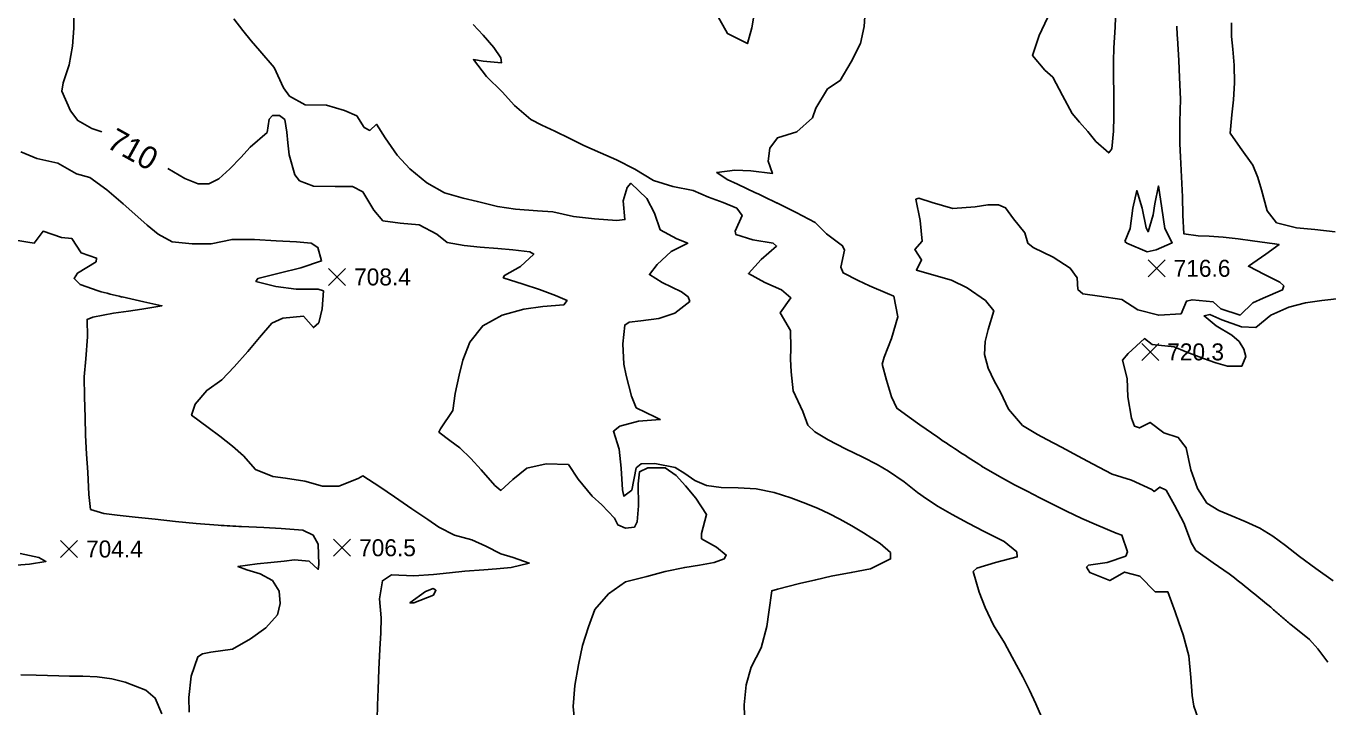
# Model space of a CAD drawing. Extents: x 2566079 to 2571326, y 424054 to 426896.
# Drawn here: x 2568340 to 2569490, y 425294 to 425896 of the extents above; entities that cross this region are included whole.
import ezdxf

# ---------------------------------------------------------------- set-up
doc = ezdxf.new("R2010")
doc.units = 0
for name, color, linetype in [('Contour_ADS_Label_Major', 7, 'Continuous'), ('Contour_ADS_Major', 7, 'Continuous'), ('Contour_ADS_Minor', 7, 'Continuous'), ('Contour_ADS_Spot_Elevation', 7, 'Continuous')]:
    doc.layers.add(name, color=color, linetype=linetype)

# ---------------------------------------------------------------- blocks, each defined once
blk = doc.blocks.new('S750')
at = {"layer": 'Contour_ADS_Spot_Elevation'}
for p, q in [((-0.5, 0.498), (0.5, -0.498)), ((-0.498, -0.5), (0.498, 0.5))]:
    blk.add_line(p, q, dxfattribs=at)

msp = doc.modelspace()

# ---------------------------------------------------------------- linework, layer by layer
at = {"layer": 'Contour_ADS_Major'}
for points in [[(2568338.3, 425981.8), (2568349.5, 425973), (2568362.5, 425958.9), (2568373.6, 425945.3), (2568379.5, 425938), (2568380.8, 425925.3), (2568381.9, 425909.7), (2568381.7, 425893.8), (2568380.6, 425877.8), (2568377.6, 425861.3), (2568372.3, 425845.4), (2568371.3, 425838.1), (2568378.8, 425820.9), (2568385.3, 425812.2), (2568397.8, 425805.3), (2568405.8, 425802.5), (2568406.5, 425802.3)], [(2569404.4, 425898.6), (2569404.5, 425886.6), (2569405.7, 425875.2), (2569406.9, 425861), (2569407.3, 425845.5), (2569406.3, 425830.5), (2569404.7, 425817.4), (2569403.2, 425801), (2569412.3, 425788.4), (2569423.4, 425772.7), (2569427.8, 425761.9), (2569431, 425751), (2569436, 425732.4), (2569444.3, 425722), (2569462, 425717.5), (2569478.1, 425716.1), (2569496.2, 425714)], [(2568464.8, 425769.9), (2568479.9, 425761), (2568491.8, 425756.2), (2568501.2, 425756.2), (2568510, 425760.8), (2568519.6, 425769.5), (2568529.3, 425779.7), (2568537.7, 425788.7), (2568552.6, 425801.7), (2568554.5, 425813.3), (2568557.4, 425816.6), (2568563.6, 425816.8), (2568568.3, 425813), (2568570, 425802), (2568570.8, 425792.6), (2568572, 425781.9), (2568577, 425764.4), (2568581.3, 425759.1), (2568593.7, 425754.2), (2568612.8, 425754), (2568628.1, 425754), (2568637.2, 425749.2), (2568647, 425733.2), (2568654.9, 425723.5), (2568670.2, 425721.6), (2568686.8, 425720), (2568702.5, 425711.8), (2568711.5, 425704.6), (2568726.8, 425701.9), (2568740.9, 425700.5), (2568756.4, 425699.1), (2568769.5, 425697.9), (2568784.6, 425696.2), (2568788.1, 425694.3), (2568776.5, 425683.4), (2568762.3, 425675.5), (2568761.2, 425673.4), (2568778.8, 425667.8), (2568793.3, 425662.9), (2568807.3, 425657.8), (2568817.5, 425653.2), (2568814.7, 425649.6), (2568796.1, 425647.9), (2568779.4, 425645.5), (2568760.1, 425640.4), (2568743, 425631), (2568731.7, 425616.6), (2568725.4, 425600.7), (2568722.3, 425587.4), (2568718.7, 425571.2), (2568716.5, 425556.2), (2568705.6, 425539.8), (2568704.3, 425537), (2568713.9, 425529.7), (2568722.7, 425523.1), (2568732.4, 425513.8), (2568741.6, 425503.7), (2568753.7, 425490), (2568759, 425485.6), (2568769.7, 425495.3), (2568782.1, 425505.2), (2568799.1, 425509.1), (2568818.8, 425508.5), (2568827.4, 425495.4), (2568839.7, 425480.6), (2568848.2, 425472.9), (2568859.5, 425461), (2568862.5, 425455.1), (2568869.1, 425452.3), (2568877, 425453.2), (2568879.6, 425457.9), (2568880.6, 425472), (2568880.5, 425491.4), (2568881.6, 425502.1), (2568889, 425505.4), (2568904.1, 425505.5), (2568913.8, 425498.6), (2568922.2, 425489.5), (2568931.3, 425478.7), (2568940.8, 425464.2), (2568936.2, 425447.4), (2568936.3, 425442.8), (2568949.6, 425435.4), (2568958.2, 425428.5), (2568956.4, 425425), (2568947.6, 425422), (2568934.6, 425419.6), (2568921.5, 425417.5), (2568904.2, 425413.9), (2568888, 425409.6), (2568869.3, 425404.8), (2568854.2, 425394.3), (2568842.1, 425380.3), (2568836.4, 425365.2), (2568831.1, 425348.6), (2568827.8, 425331.6), (2568824.5, 425313.1), (2568822.8, 425294.6), (2568824.1, 425282.6)], [(2569502.6, 425655.2), (2569484.2, 425653.3), (2569469.8, 425651.1), (2569455.2, 425647.4), (2569439.2, 425640.3), (2569426.1, 425629.3), (2569413.4, 425630.1), (2569396, 425636.3), (2569385.4, 425640.8), (2569380.3, 425639.7), (2569391, 425630.9), (2569404.9, 425622.8), (2569411.3, 425617), (2569415.4, 425610.4), (2569417.1, 425603.9), (2569413.7, 425595.4), (2569401, 425595.4), (2569390.8, 425598.3), (2569379.9, 425602.1), (2569363.5, 425608.3), (2569353.9, 425612.3), (2569334.3, 425614.4), (2569327.7, 425619.6), (2569313.2, 425606.4), (2569308.2, 425600.7), (2569312.4, 425584.5), (2569312.9, 425568.1), (2569316.3, 425549.4), (2569318.8, 425542.4), (2569323.2, 425540.7), (2569332.8, 425545.6), (2569344.7, 425536.5), (2569357.5, 425532.3), (2569364.5, 425523.1), (2569368.7, 425503.7), (2569374.5, 425487.3), (2569382.7, 425474.4), (2569393.4, 425467.7), (2569403.9, 425463.4), (2569416.7, 425458.2), (2569429.6, 425452.1), (2569441.1, 425445.1), (2569452.2, 425436.9), (2569464.5, 425427.3), (2569479, 425416.5), (2569494.2, 425405.8)]]:
    msp.add_lwpolyline(points, dxfattribs=at)
at = {"layer": 'Contour_ADS_Minor'}
for points in [[(2569080.8, 425908.4), (2569080.1, 425895.4), (2569076.8, 425880.2), (2569068.5, 425864.2), (2569058.8, 425847.6), (2569047.6, 425840.1), (2569037.2, 425823.3), (2569034.3, 425814.6), (2569020.6, 425802.2), (2569003.4, 425797), (2568996.8, 425787.7), (2568995.1, 425776.2), (2568999, 425765.4), (2568980, 425767.7), (2568965.8, 425768.4), (2568949.8, 425766.4), (2568959.1, 425760.3), (2568968.1, 425756), (2568984, 425748.5)], [(2569241.9, 425903), (2569234.7, 425887.4), (2569228.8, 425869.8), (2569239.7, 425856.8), (2569246.8, 425850.4), (2569255.1, 425834.3), (2569263.9, 425818.3), (2569270.3, 425810.7), (2569277.5, 425802.6), (2569284.7, 425793.7), (2569296.1, 425783.6), (2569298.9, 425787.1), (2569300.3, 425802.9), (2569300.6, 425815.6), (2569300.6, 425824.1), (2569300.5, 425836.4), (2569300.3, 425850.8), (2569300.4, 425864.8), (2569300.4, 425864.8), (2569300.7, 425876.4), (2569301.7, 425894.6), (2569302.4, 425911.7)], [(2568523.1, 425902), (2568531, 425891.9), (2568538.6, 425882.5), (2568546, 425873.8), (2568558.9, 425859), (2568567.2, 425841.1), (2568572.3, 425833.9), (2568586.2, 425826), (2568604.9, 425825.8), (2568620.8, 425821.1), (2568631.8, 425816.5), (2568638.3, 425806.2), (2568643.3, 425803.5), (2568649.2, 425808.9), (2568656.9, 425796.9), (2568667.6, 425781.5), (2568678.8, 425769.6), (2568693.6, 425757.2), (2568709.4, 425748.3), (2568725.9, 425743.8), (2568738.4, 425740.6), (2568756.1, 425736.3), (2568771.9, 425733.9), (2568791.4, 425732.6), (2568804.9, 425731.7), (2568823.1, 425727.6), (2568841.8, 425725.4), (2568861.6, 425723.8), (2568868.7, 425724.8), (2568867.1, 425741.2), (2568870.6, 425753.1), (2568874, 425756.9), (2568887.9, 425743.4), (2568894.8, 425730.3), (2568899.8, 425715.8), (2568914.4, 425707.8), (2568924.1, 425703.8), (2568909.6, 425696.5), (2568897.1, 425685), (2568890.3, 425676.1), (2568901.7, 425669.3), (2568918.6, 425661), (2568924.6, 425656.4), (2568926, 425652.4), (2568912.9, 425642.2), (2568898.6, 425637.3), (2568882.8, 425635.4), (2568872.3, 425634.2), (2568868.5, 425631.6), (2568866.7, 425614.9), (2568867.8, 425597), (2568869.7, 425586.9), (2568874.5, 425568.9), (2568878.7, 425558.5), (2568895.8, 425550.2), (2568899.9, 425548.1), (2568880.7, 425546.8), (2568864.1, 425542.2), (2568858.5, 425537.8), (2568863.7, 425522), (2568865.2, 425505.3), (2568866.4, 425486.2), (2568867.8, 425480.4), (2568874.7, 425485.9), (2568878.7, 425505.4), (2568883.1, 425509), (2568895.2, 425509.3), (2568913, 425505.7), (2568921.5, 425500.5), (2568930.3, 425494.4), (2568940.8, 425489.8), (2568953.8, 425488), (2568968.8, 425487.7), (2568984.7, 425486.8), (2569000.5, 425483.8), (2569015.3, 425479.1), (2569028.4, 425474.1), (2569039.3, 425469.5), (2569048.9, 425465.1), (2569058.6, 425460.2), (2569069.1, 425454.3), (2569079.5, 425448.2), (2569094, 425438.6)], [(2568734.7, 425897.2), (2568743.5, 425887.5), (2568752.8, 425876.6), (2568759, 425867.7), (2568759.7, 425863.2), (2568743.5, 425864.7), (2568734.8, 425866), (2568746.5, 425851.1), (2568760.3, 425837.7), (2568771, 425825.4), (2568785.4, 425813), (2568795.3, 425808.2), (2568806.6, 425802.8), (2568820, 425796.3), (2568832.4, 425790.3), (2568847.1, 425783.6), (2568861.3, 425777.4), (2568877.3, 425769.3), (2568893.9, 425759.4), (2568911, 425753.9), (2568928.9, 425750.5), (2568942.4, 425744.6), (2568955.5, 425739.8), (2568967.5, 425734.7), (2568972.1, 425728.3), (2568966.1, 425714.6), (2568966.7, 425711.5), (2568981.6, 425707), (2568999.6, 425704), (2569002.6, 425701.3), (2568988.9, 425689.5), (2568977.7, 425677.2), (2568992.4, 425669.1), (2569007.1, 425662.7), (2569015.2, 425655.7), (2569005.7, 425642.5), (2569015, 425626.8), (2569015.1, 425611.3), (2569015, 425601.4), (2569015.5, 425590.4), (2569017.4, 425573.4), (2569025.7, 425555.2), (2569030.1, 425543.1), (2569036.3, 425537.2), (2569048.2, 425530.1), (2569063.5, 425522.4), (2569078.8, 425515), (2569091.5, 425508.4), (2569101.5, 425502.6), (2569115.4, 425493.1), (2569127.2, 425483.8), (2569135.2, 425478), (2569145.3, 425471.4), (2569157.6, 425464.2), (2569171.9, 425456.5), (2569186, 425449.3), (2569203.8, 425440.3), (2569214.9, 425431.2), (2569215.2, 425426.8), (2569195.9, 425422), (2569179.5, 425416.9), (2569176.4, 425413.9), (2569181.7, 425395.6), (2569186.8, 425382.1), (2569194.2, 425366.4), (2569204.1, 425350.8), (2569210.8, 425338.4), (2569220.2, 425320.8), (2569226.1, 425309.2), (2569231.8, 425297.1), (2569236.6, 425285.7)], [(2568982.7, 425906.1), (2568980.9, 425894), (2568976.9, 425880.2), (2568959.4, 425889.1), (2568950, 425905.8)], [(2569356.8, 425885.1), (2569357.9, 425865.2), (2569358.6, 425850.1), (2569359.4, 425831.1), (2569359, 425811.1), (2569359, 425791.8), (2569359.6, 425780.3), (2569360.3, 425762.4), (2569361.1, 425744.9), (2569361.6, 425728.7), (2569362.4, 425712.1), (2569375, 425710.5), (2569384.9, 425710.1), (2569397, 425709.2), (2569410.3, 425707.8), (2569423.1, 425706.1), (2569442.6, 425703.4), (2569446.5, 425702.6), (2569434.7, 425694.1), (2569419.4, 425683.6), (2569433.6, 425676.3), (2569447.1, 425669.6), (2569450.7, 425666.1), (2569449.5, 425662.6), (2569432.4, 425655.2), (2569423.4, 425651.1), (2569412.2, 425640.4), (2569395.1, 425645.9), (2569388.3, 425652), (2569369.7, 425653.9), (2569364.7, 425652.7), (2569360, 425641.6), (2569340.3, 425640.3), (2569321.7, 425645.1), (2569307.6, 425654.3), (2569288, 425657.2), (2569273.2, 425659.2), (2569268.8, 425663.1), (2569268.2, 425673.4), (2569262, 425681.9), (2569247.1, 425691.6), (2569229.4, 425700.1), (2569224.6, 425703.8), (2569221.9, 425713.1), (2569211.8, 425725.5), (2569205, 425735.2), (2569198.7, 425737.9), (2569189.3, 425737.8), (2569178.1, 425736), (2569158.4, 425734.4), (2569140.1, 425739.7), (2569128.4, 425743.7), (2569125.7, 425742.7), (2569129.4, 425724), (2569131.1, 425705.8), (2569124.9, 425698.3), (2569130.7, 425689.2), (2569126.1, 425680.1), (2569139.4, 425676.2), (2569157.2, 425671.1), (2569171, 425664.4), (2569187.2, 425653.2), (2569194.5, 425644.1), (2569189.6, 425627.6), (2569186.9, 425617.2), (2569186.4, 425605.5), (2569189.6, 425593.6), (2569194.9, 425582.4), (2569200.3, 425572.4), (2569207.4, 425557.3), (2569219.9, 425542.8), (2569233.2, 425534.8), (2569241.5, 425530.5), (2569254.3, 425523.6), (2569269, 425515.8), (2569281.7, 425509), (2569299.1, 425499.9), (2569316.3, 425494.5), (2569334, 425486.5), (2569336.1, 425484.6), (2569341.3, 425488.5), (2569346.8, 425485.7), (2569354.1, 425472.6), (2569362.5, 425457), (2569369.2, 425439.1), (2569373.1, 425432.6), (2569388.4, 425421.5), (2569402.4, 425411.9)], [(2568335, 425784.6), (2568349.1, 425778.8), (2568367.7, 425774.5), (2568384.3, 425765.2), (2568396, 425762), (2568411.1, 425750.9), (2568425.4, 425738.6), (2568435.7, 425729.5), (2568446.6, 425719.9), (2568456.3, 425712), (2568468.8, 425705), (2568486.5, 425703.4), (2568503.3, 425703.4), (2568521.6, 425707.2), (2568541.3, 425707.1), (2568560.7, 425705.9), (2568578.6, 425705), (2568591.5, 425703.8), (2568597.4, 425700.2), (2568600.7, 425688.3), (2568582.4, 425682.2), (2568563.2, 425677.4), (2568544.3, 425672.7), (2568542.7, 425670.1), (2568560.3, 425665.7), (2568578.1, 425663.4), (2568597.8, 425663.2), (2568602.3, 425661.8), (2568601.3, 425646), (2568598.2, 425633.6), (2568593.5, 425629.3), (2568584.7, 425639.4), (2568566.6, 425637.7), (2568556.8, 425633.2), (2568545.8, 425620.6), (2568535.5, 425608.3), (2568523.5, 425594.6), (2568512.5, 425583.3), (2568499.2, 425573.9), (2568489, 425561.8), (2568485.8, 425551.9), (2568500.4, 425541), (2568510.7, 425533.5), (2568522, 425524.6), (2568531.6, 425516), (2568542.2, 425503.9), (2568557.7, 425497.9), (2568568.9, 425496.3), (2568585.9, 425493.6), (2568601.6, 425489.3), (2568616, 425489.4), (2568632.9, 425496), (2568637.2, 425498.3), (2568652.2, 425488.6), (2568665.2, 425479.8), (2568680.5, 425469.4), (2568694.5, 425459.9), (2568704.4, 425453.2), (2568718, 425446.1), (2568733.5, 425441.9), (2568745.9, 425436.4), (2568759, 425429.4), (2568769.8, 425426.4), (2568784.2, 425421.4), (2568768.1, 425417.6), (2568755.1, 425416.2), (2568744, 425415.3), (2568727.3, 425414.2), (2568713.6, 425412.8)], [(2569003, 425739.4), (2569019.9, 425731.1), (2569036.6, 425722.2), (2569046.8, 425712.2), (2569060.9, 425701.7), (2569062.7, 425697.8), (2569059.5, 425682.8), (2569061.5, 425677.7), (2569074.7, 425670.9), (2569084.8, 425666.3), (2569100.6, 425659.6), (2569106.2, 425657.1), (2569109.7, 425639), (2569104.1, 425619.8), (2569097.8, 425603.2), (2569096, 425597.1), (2569099.8, 425583), (2569104.1, 425568.2), (2569108.8, 425558.1), (2569119.7, 425550.1), (2569129.2, 425543.4), (2569145.1, 425532.5)], [(2568322.1, 425708), (2568341.3, 425704.8), (2568346.9, 425704), (2568354.6, 425714.4), (2568370.8, 425708.9), (2568380.1, 425708), (2568388.3, 425695.4), (2568401.9, 425690.8), (2568401.6, 425687.5), (2568385.2, 425677.5), (2568382.1, 425672.8), (2568387.3, 425667.5), (2568403.2, 425661.8)], [(2568424.5, 425656.4), (2568443.6, 425652.2), (2568459.6, 425648.6), (2568441.8, 425645.7), (2568430.1, 425644), (2568416.9, 425642), (2568398.5, 425638.7), (2568393.6, 425636.6), (2568393.8, 425621.3), (2568392.4, 425601.7), (2568390.9, 425586), (2568391.3, 425568.2), (2568391.8, 425550), (2568392.2, 425534.2), (2568393.1, 425517.6), (2568394.1, 425501.8), (2568395, 425482), (2568396.7, 425468.7), (2568408.2, 425465.2), (2568420.2, 425463.8), (2568436.1, 425462), (2568453.8, 425460.1), (2568471.6, 425458.2), (2568489.9, 425456.4), (2568509.4, 425454.9)], [(2569183.8, 425507.1), (2569199.7, 425497.7), (2569212.7, 425490.6), (2569224.1, 425484.8), (2569235.1, 425479.1), (2569246.5, 425473.3), (2569258.8, 425467.2), (2569272.3, 425460.8), (2569285.3, 425455), (2569302.7, 425447.9), (2569307.7, 425446.1), (2569312.6, 425431.2), (2569311.1, 425427.5), (2569294.6, 425421.9), (2569278.3, 425419.4), (2569276.5, 425417.8), (2569279.4, 425412.9), (2569297, 425405.9), (2569310, 425413.4), (2569323.5, 425409.9), (2569337.2, 425396), (2569348.3, 425395.9), (2569354.6, 425378.4), (2569357.9, 425369), (2569361.7, 425357.9), (2569366.9, 425339.3), (2569368.6, 425320.2), (2569369.8, 425304.5), (2569371.1, 425295.1), (2569375, 425284.1)], [(2568530, 425453.6), (2568549.6, 425452.7), (2568565.1, 425452), (2568584.1, 425450.4), (2568593.4, 425446), (2568597.6, 425438.2), (2568598.4, 425420.1), (2568597.8, 425415.8), (2568589.6, 425423.1), (2568576.9, 425424.1), (2568567.5, 425423.2), (2568555.8, 425421.9), (2568543.8, 425420.6), (2568526.8, 425418.4), (2568534.6, 425415.4), (2568546.4, 425412), (2568557.2, 425405.9), (2568563.1, 425396.5), (2568564.2, 425385.6), (2568561.8, 425375.8), (2568551.4, 425364.1), (2568537.9, 425354.4), (2568522, 425345.3), (2568502.8, 425342.6), (2568495.4, 425341.3), (2568491.5, 425338.6), (2568485.4, 425321.6), (2568483.4, 425302.5), (2568483.7, 425289.7)], [(2569094, 425438.6), (2569103.2, 425430.6), (2569103.4, 425425.1), (2569085.7, 425416.4), (2569068.6, 425412.9), (2569051, 425409.8), (2569037.3, 425406.7), (2569022.8, 425403.2), (2569003.5, 425398.4), (2568998.3, 425397), (2568995.8, 425377.9), (2568994, 425365.4), (2568989.1, 425346.4), (2568980.3, 425329.5), (2568975.8, 425313.7), (2568973.9, 425296.1), (2568974.5, 425277)], [(2568334.3, 425429.9), (2568351, 425426.2), (2568357.2, 425422.8), (2568342.6, 425420.4), (2568331.1, 425419.4)], [(2568713.6, 425412.8), (2568699.6, 425411.2), (2568682.1, 425410.2), (2568662.5, 425411), (2568654.4, 425405.7), (2568651.9, 425389.8), (2568653.3, 425373.1), (2568652.9, 425359.9), (2568652.2, 425345.3), (2568651.4, 425327.5), (2568650.7, 425310.1), (2568650.1, 425295.8), (2568649.8, 425283.6)], [(2569458.3, 425366), (2569473.5, 425353.8), (2569480.7, 425345.5), (2569489.7, 425333.8)], [(2568335, 425322.7), (2568348.6, 425322.3), (2568368.5, 425321.8), (2568378.1, 425321.6), (2568389.7, 425321.5), (2568402.5, 425320.8), (2568415.4, 425319.2), (2568427.3, 425316.3), (2568445.3, 425309), (2568453.7, 425302.2), (2568459.7, 425288.1)]]:
    msp.add_lwpolyline(points, dxfattribs=at)
for points in [[(2569310.2, 425705.3), (2569315.1, 425716.8), (2569317.3, 425734.8), (2569320.8, 425750.4), (2569325.7, 425734.9), (2569329.1, 425717.4), (2569330.8, 425714), (2569335.2, 425728.9), (2569336.7, 425738.8), (2569340, 425754.5), (2569343.1, 425734.8), (2569345.5, 425716.8), (2569352.2, 425704.3), (2569338, 425697.9), (2569329.9, 425696.4), (2569312.1, 425703.8), (2569310.2, 425705.3)], [(2568692.4, 425396.4), (2568699.4, 425398.8), (2568701.7, 425397.4), (2568699.5, 425393.1), (2568682.2, 425386.2), (2568678.7, 425386.2), (2568692.4, 425396.4)]]:
    msp.add_lwpolyline(points, close=True, dxfattribs=at)
for centre, radius, start, end in [((2562316.5, 425483.7), 7051.7, 3.26305, 3.349), ((2566542.1, 420625.3), 5675.4, 64.3028, 64.5153), ((2568517.5, 426067.7), 421.7, 254.281, 257.2671), ((2569961.8, 426729.6), 1449.2, 235.6972, 236.6245), ((2569648.5, 426251.8), 877.8, 236.5472, 238.0366), ((2568602.3, 426819.5), 1367.8, 266.1056, 266.973), ((2569040, 424929.9), 603, 50.768, 53.0666), ((2568498.7, 424266.3), 1459.4, 49.7497, 50.784), ((2568120, 423820.4), 2044.4, 49.4165, 49.7225), ((2569927.3, 425926.4), 730.8, 229.2155, 230.0715)]:
    msp.add_arc(centre, radius, start, end, dxfattribs=at)

# ---------------------------------------------------------------- block references
at = {"layer": 'Contour_ADS_Spot_Elevation', "xscale": 15, "yscale": 15}
for p in [(2569338.4, 425681.7), (2568614.4, 425674.1), (2569332.7, 425607.9), (2568377.6, 425433.8), (2568618.8, 425434.9)]:
    msp.add_blockref('S750', p, dxfattribs=at)

# ---------------------------------------------------------------- texts
at = {"layer": 'Contour_ADS_Label_Major'}
msp.add_text('710', height=20, rotation=330.9499, dxfattribs=at).set_placement((2568409.7, 425789))
at = {"layer": 'Contour_ADS_Spot_Elevation'}
for s, p in [('716.6', (2569353.4, 425674.2)), ('708.4', (2568629.4, 425666.6)), ('720.3', (2569347.7, 425600.4)), ('704.4', (2568392.6, 425426.3)), ('706.5', (2568633.8, 425427.4))]:
    msp.add_text(s, height=15, dxfattribs=at).set_placement(p)

doc.saveas('drawing.dxf')
